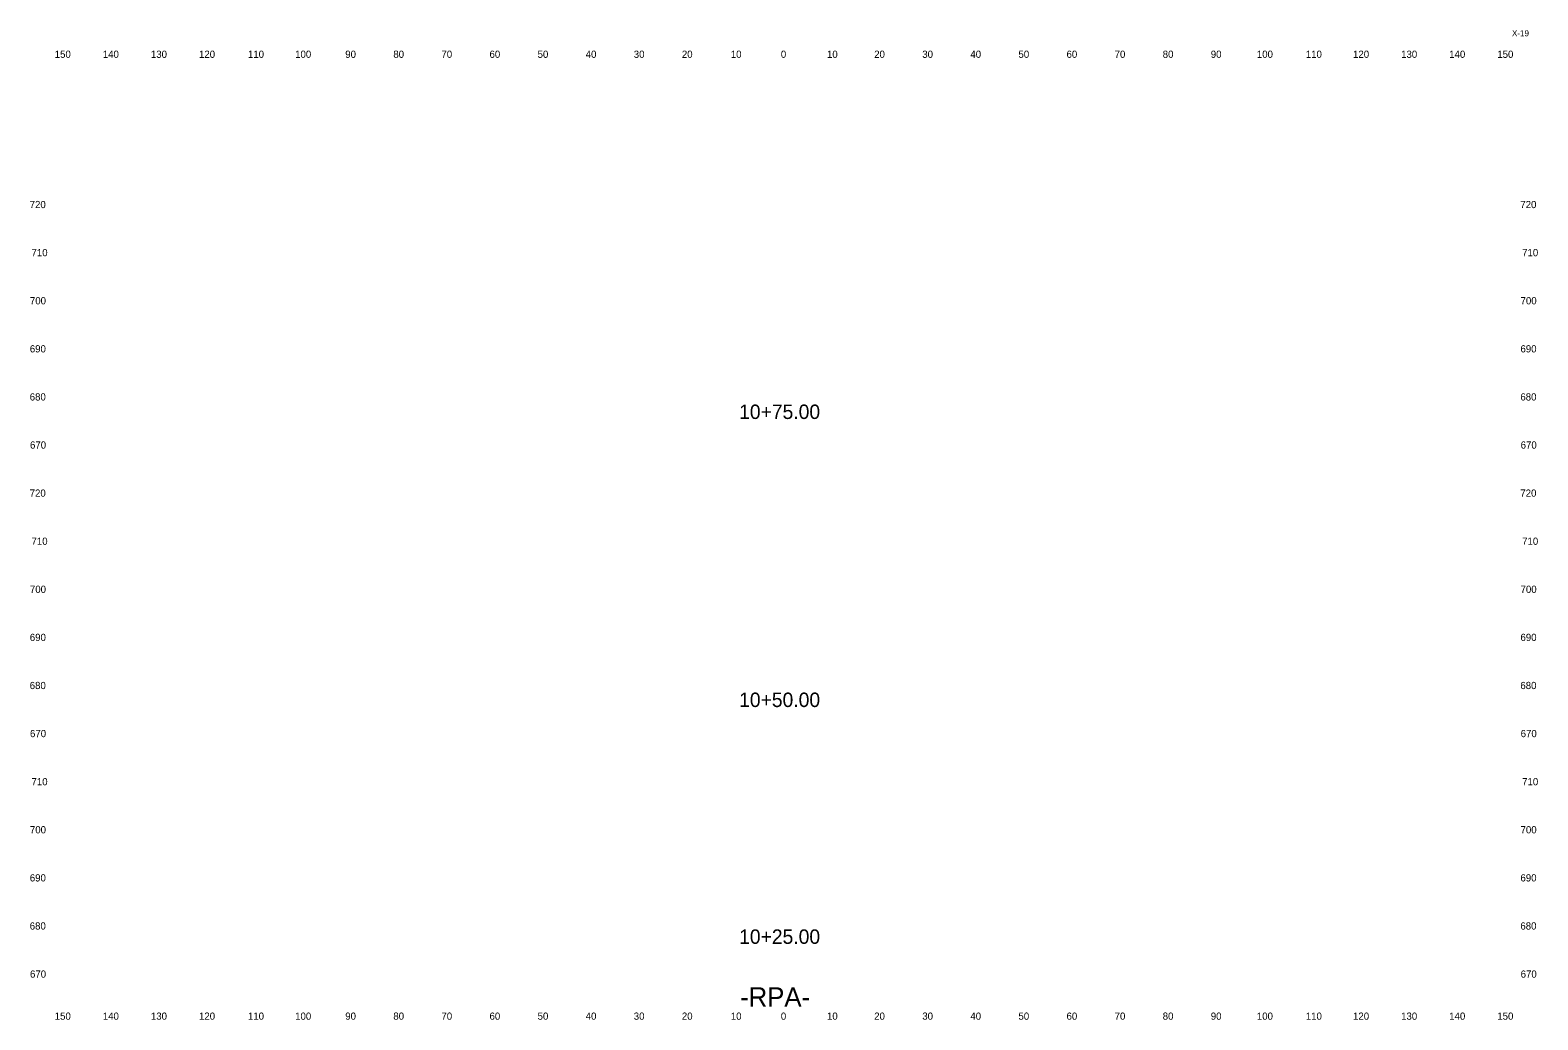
# Model space of a CAD drawing. Extents: x 3 to 317, y 1 to 867.
# Drawn here: x 3.3 to 316.9, y 1.2 to 207 of the extents above; entities that cross this region are included whole.
import ezdxf

# ---------------------------------------------------------------- set-up
doc = ezdxf.new("R2010")
doc.units = 0
for name, color, linetype in [('Prop XS Alignment Label', 7, 'Continuous'), ('Prop XS Elevation Labels', 7, 'Continuous'), ('Prop XS Offset Labels', 7, 'Continuous'), ('Prop XS Sheet Number', 7, 'Continuous'), ('Prop XS Station Labels', 7, 'Continuous')]:
    doc.layers.add(name, color=color, linetype=linetype)

msp = doc.modelspace()

# ---------------------------------------------------------------- texts
at = {"layer": 'Prop XS Alignment Label'}
msp.add_text('-RPA-', height=4, dxfattribs=at).set_placement((150.97, 4))
at = {"layer": 'Prop XS Elevation Labels'}
for s, p in [('720', (3.23, 170)), ('720', (313.23, 170)), ('710', (3.61, 160)), ('710', (313.61, 160)), ('700', (3.28, 150)), ('700', (313.28, 150)), ('690', (3.26, 140)), ('690', (313.26, 140)), ('680', (3.24, 130)), ('680', (313.24, 130)), ('670', (3.3, 120)), ('670', (313.3, 120)), ('720', (3.23, 110)), ('720', (313.23, 110)), ('710', (3.61, 100)), ('710', (313.61, 100)), ('700', (3.28, 90)), ('700', (313.28, 90)), ('690', (3.26, 80)), ('690', (313.26, 80)), ('680', (3.24, 70)), ('680', (313.24, 70)), ('670', (3.3, 60)), ('670', (313.3, 60)), ('710', (3.61, 50)), ('710', (313.61, 50)), ('700', (3.28, 40)), ('700', (313.28, 40)), ('690', (3.26, 30)), ('690', (313.26, 30)), ('680', (3.24, 20)), ('680', (313.24, 20)), ('670', (3.3, 10)), ('670', (313.3, 10))]:
    msp.add_text(s, height=1.5, dxfattribs=at).set_placement(p)
at = {"layer": 'Prop XS Offset Labels'}
for s, p in [('150', (8.44, 201.25)), ('140', (18.44, 201.25)), ('130', (28.44, 201.25)), ('120', (38.44, 201.25)), ('110', (48.62, 201.25)), ('100', (58.44, 201.25)), ('90', (68.86, 201.25)), ('80', (78.86, 201.25)), ('70', (88.86, 201.25)), ('60', (98.86, 201.25)), ('50', (108.86, 201.25)), ('40', (118.86, 201.25)), ('30', (128.86, 201.25)), ('20', (138.86, 201.25)), ('10', (149.04, 201.25)), ('0', (159.45, 201.25)), ('10', (169.04, 201.25)), ('20', (178.86, 201.25)), ('30', (188.86, 201.25)), ('40', (198.86, 201.25)), ('50', (208.86, 201.25)), ('60', (218.86, 201.25)), ('70', (228.86, 201.25)), ('80', (238.86, 201.25)), ('90', (248.86, 201.25)), ('100', (258.44, 201.25)), ('110', (268.62, 201.25)), ('120', (278.44, 201.25)), ('130', (288.44, 201.25)), ('140', (298.44, 201.25)), ('150', (308.44, 201.25)), ('150', (8.44, 1.25)), ('140', (18.44, 1.25)), ('130', (28.44, 1.25)), ('120', (38.44, 1.25)), ('110', (48.62, 1.25)), ('100', (58.44, 1.25)), ('90', (68.86, 1.25)), ('80', (78.86, 1.25)), ('70', (88.86, 1.25)), ('60', (98.86, 1.25)), ('50', (108.86, 1.25)), ('40', (118.86, 1.25)), ('30', (128.86, 1.25)), ('20', (138.86, 1.25)), ('10', (149.04, 1.25)), ('0', (159.45, 1.25)), ('10', (169.04, 1.25)), ('20', (178.86, 1.25)), ('30', (188.86, 1.25)), ('40', (198.86, 1.25)), ('50', (208.86, 1.25)), ('60', (218.86, 1.25)), ('70', (228.86, 1.25)), ('80', (238.86, 1.25)), ('90', (248.86, 1.25)), ('100', (258.44, 1.25)), ('110', (268.62, 1.25)), ('120', (278.44, 1.25)), ('130', (288.44, 1.25)), ('140', (298.44, 1.25)), ('150', (308.44, 1.25))]:
    msp.add_text(s, height=1.5, dxfattribs=at).set_placement(p)
at = {"layer": 'Prop XS Sheet Number'}
msp.add_text('X-19', height=1.25, dxfattribs=at).set_placement((311.5, 205.74))
at = {"layer": 'Prop XS Station Labels'}
for s, p in [('10+75.00', (150.77, 126.16)), ('10+50.00', (150.77, 66.27)), ('10+25.00', (150.77, 17.03))]:
    msp.add_text(s, height=3, dxfattribs=at).set_placement(p)

doc.saveas('drawing.dxf')
